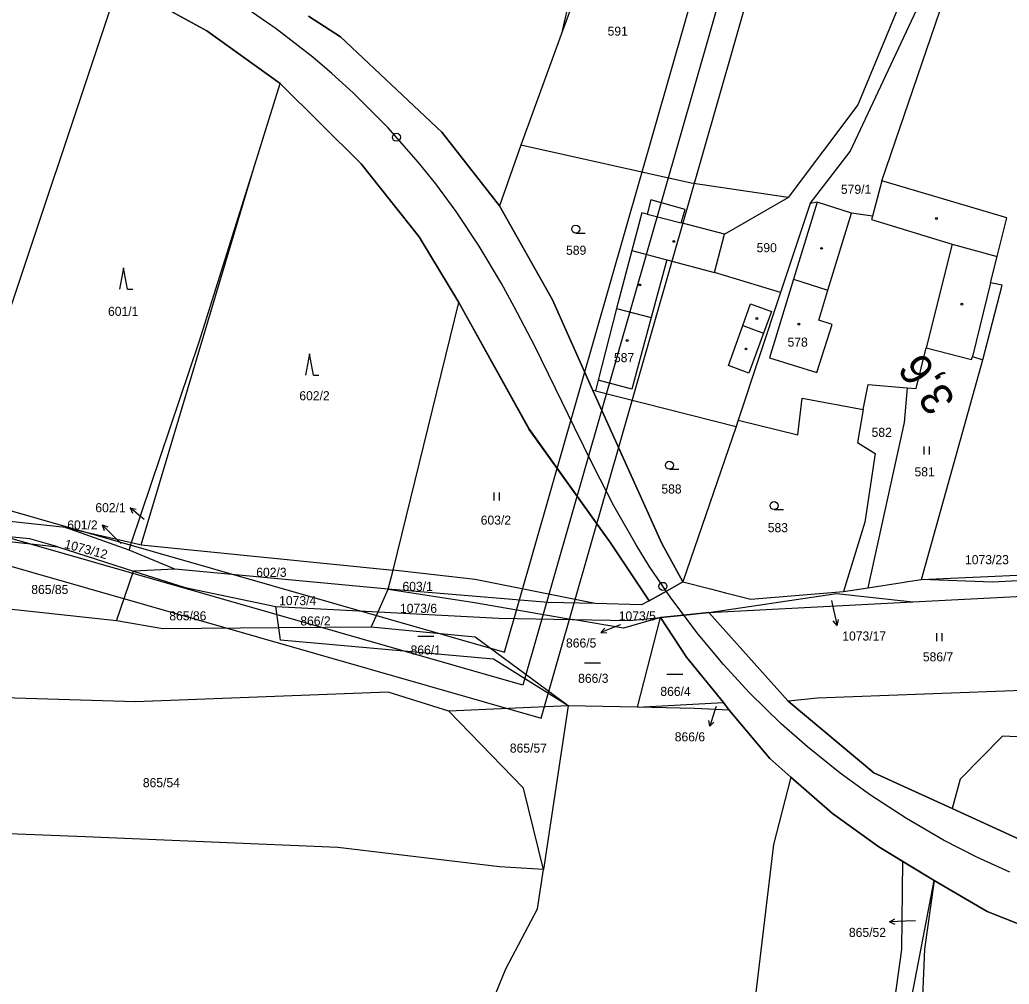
# Model space of a CAD drawing. Extents: x -738085 to -734306, y -1122197 to -1119753.
# Drawn here: x -736906 to -736720.5, y -1121765.8 to -1121585.1 of the extents above; entities that cross this region are included whole.
import ezdxf

# ---------------------------------------------------------------- set-up
doc = ezdxf.new("R2010")
doc.units = 0
for name, color, linetype in [('Hranice parcel', 7, 'Continuous'), ('Parcelní čísla', 7, 'Continuous'), ('Pop  PČ popisy', 7, 'Continuous'), ('SŽDC', 7, 'Continuous'), ('Vnitřní kresba', 7, 'Continuous'), ('Vrstva 1', 7, 'Continuous'), ('Vrstva 53', 7, 'Continuous'), ('Vrstva 7', 7, 'Continuous'), ('Značky budov', 7, 'Continuous'), ('Značky kultur', 7, 'Continuous')]:
    doc.layers.add(name, color=color, linetype=linetype)

msp = doc.modelspace()

# ---------------------------------------------------------------- linework, layer by layer
at = {"layer": 'Hranice parcel'}
for p, q in [((-736804.2, -1121587.16), (-736798.31, -1121561.29)), ((-736795.38, -1121563.11), (-736804.2, -1121587.16)), ((-736744.38, -1121615.25), (-736731.13, -1121576.64)), ((-736920.64, -1121677.71), (-736887.39, -1121578.1)), ((-736887.39, -1121578.1), (-736870.91, -1121587.14)), ((-736870.91, -1121587.14), (-736857.16, -1121597.03)), ((-736804.2, -1121587.16), (-736812.06, -1121608.56)), ((-736862.23, -1121613.22), (-736857.16, -1121597.03)), ((-736812.06, -1121608.56), (-736816.01, -1121619.92)), ((-736883.23, -1121683.48), (-736862.23, -1121613.22)), ((-736773.84, -1121625.27), (-736761.91, -1121618.36)), ((-736757.76, -1121619.52), (-736763.38, -1121636.17)), ((-736816.01, -1121619.92), (-736806.1, -1121637.54)), ((-736763.38, -1121636.17), (-736771.28, -1121660.12)), ((-736836, -1121688.2), (-736823.69, -1121638.07)), ((-736806.1, -1121637.54), (-736798.56, -1121654.54)), ((-736736.91, -1121689.98), (-736725.44, -1121648.79)), ((-736798.06, -1121654.63), (-736798.56, -1121654.54)), ((-736798.06, -1121654.63), (-736771.68, -1121661.3)), ((-736771.28, -1121660.12), (-736771.68, -1121661.3)), ((-736771.68, -1121661.3), (-736781.66, -1121690.42)), ((-736897.44, -1121680.24), (-736920.64, -1121677.71)), ((-736897.44, -1121680.24), (-736885.01, -1121683.07)), ((-736885.49, -1121684.49), (-736897.44, -1121680.24)), ((-736898.85, -1121683.84), (-736884.64, -1121688.4)), ((-736885.49, -1121684.49), (-736885.01, -1121683.07)), ((-736876.89, -1121688.05), (-736885.49, -1121684.49)), ((-736885.01, -1121683.07), (-736883.23, -1121683.48)), ((-736883.23, -1121683.48), (-736836, -1121688.2)), ((-736876.89, -1121688.05), (-736884.64, -1121688.4)), ((-736836.89, -1121691.81), (-736876.89, -1121688.05)), ((-736836.89, -1121691.81), (-736836, -1121688.2)), ((-736887.88, -1121697.71), (-736884.64, -1121688.4)), ((-736736.91, -1121689.98), (-736714.87, -1121688.97)), ((-736838.79, -1121696.05), (-736836.89, -1121691.81)), ((-736751.55, -1121692.22), (-736746.95, -1121691.53)), ((-736857.43, -1121699.06), (-736857.96, -1121695.06)), ((-736857.96, -1121695.06), (-736838.79, -1121696.05)), ((-736776.82, -1121696.15), (-736738.53, -1121694.16)), ((-736840.07, -1121698.92), (-736838.79, -1121696.05)), ((-736790.17, -1121713.93), (-736785.85, -1121697.11)), ((-736761.9, -1121712.81), (-736776.82, -1121696.15)), ((-736840.07, -1121698.92), (-736857.43, -1121699.06)), ((-736803.14, -1121713.67), (-736825.52, -1121714.65)), ((-736803.14, -1121713.67), (-736807.76, -1121744.34)), ((-736790.17, -1121713.93), (-736803.14, -1121713.67)), ((-736790.17, -1121713.93), (-736774.04, -1121713.02)), ((-736774.04, -1121713.02), (-736772.96, -1121714.48)), ((-736740.39, -1121742.85), (-736734.55, -1121746.43))]:
    msp.add_line(p, q, dxfattribs=at)
for points in [[(-736737.5, -1121573.48), (-736748.87, -1121600.98), (-736761.91, -1121618.36)], [(-736757.76, -1121619.52), (-736750.29, -1121609.72), (-736734.46, -1121575.99)], [(-736816.01, -1121619.92), (-736826.87, -1121606.1), (-736845.88, -1121588.28), (-736851.83, -1121584.35)], [(-736857.16, -1121597.03), (-736842, -1121612.07), (-736831.1, -1121625.74), (-736823.69, -1121638.07)], [(-736761.91, -1121618.36), (-736780.08, -1121615.71), (-736812.06, -1121608.56)], [(-736885.01, -1121683.07), (-736872.32, -1121645.4), (-736862.23, -1121613.22)], [(-736744.38, -1121615.25), (-736746.11, -1121621.84), (-736750.01, -1121621.31), (-736756.49, -1121619.27), (-736757.76, -1121619.52)], [(-736725.44, -1121648.79), (-736721.76, -1121634.82), (-736723.95, -1121634.36), (-736722.72, -1121629.46), (-736720.89, -1121622.16), (-736744.38, -1121615.25)], [(-736773.84, -1121625.27), (-736781.96, -1121623.14), (-736781.22, -1121620.6), (-736787.66, -1121618.81), (-736788.34, -1121621.5), (-736789.34, -1121621.24), (-736791.21, -1121628.32), (-736794.07, -1121639.16), (-736797.54, -1121652.6), (-736798.06, -1121654.63)], [(-736763.38, -1121636.17), (-736775.71, -1121632.4), (-736773.84, -1121625.27)], [(-736823.69, -1121638.07), (-736810.44, -1121661.83), (-736795.22, -1121683.12), (-736787.95, -1121693.96)], [(-736739.59, -1121654.03), (-736737.89, -1121654.18), (-736736.01, -1121646.58), (-736727.53, -1121648.73), (-736727.35, -1121648.19), (-736725.44, -1121648.79)], [(-736798.56, -1121654.54), (-736785.62, -1121683.26), (-736781.66, -1121690.42)], [(-736747.85, -1121658.12), (-736746.89, -1121653.43), (-736739.59, -1121654.03)], [(-736739.59, -1121654.03), (-736740.18, -1121660.52), (-736746.95, -1121691.53)], [(-736771.28, -1121660.12), (-736760.1, -1121662.86), (-736759.3, -1121656.01), (-736747.85, -1121658.12)], [(-736747.85, -1121658.12), (-736748.92, -1121664.28), (-736745.58, -1121666.34), (-736747.55, -1121679.23), (-736751.55, -1121692.22)], [(-736898.85, -1121683.84), (-736904.07, -1121682.33), (-736920.51, -1121680.8)], [(-736920.32, -1121682.51), (-736910.21, -1121682.63), (-736898.85, -1121683.84)], [(-736798.07, -1121694.5), (-736820.58, -1121689.98), (-736836, -1121688.2)], [(-736884.64, -1121688.4), (-736875, -1121691.49), (-736857.96, -1121695.06)], [(-736746.95, -1121691.53), (-736740.51, -1121690.54), (-736739.5, -1121690.38), (-736736.91, -1121689.98)], [(-736701.11, -1121689.29), (-736723.58, -1121690.47), (-736736.91, -1121689.98)], [(-736798.07, -1121694.5), (-736806.94, -1121694.27), (-736836.89, -1121691.81)], [(-736836.89, -1121691.81), (-736820.75, -1121694.29), (-736802.33, -1121697.47)], [(-736787.95, -1121693.96), (-736784.72, -1121692.14), (-736781.66, -1121690.42)], [(-736781.66, -1121690.42), (-736776.45, -1121691.74), (-736773.66, -1121692.45), (-736768.91, -1121693.66), (-736751.55, -1121692.22)], [(-736776.82, -1121696.15), (-736752.86, -1121692.61), (-736738.53, -1121694.16)], [(-736738.53, -1121694.16), (-736708.22, -1121692.59), (-736702.57, -1121692.29)], [(-736887.88, -1121697.71), (-736910.4, -1121695.27), (-736918.95, -1121695.03)], [(-736787.95, -1121693.96), (-736789.39, -1121694.72), (-736798.07, -1121694.5)], [(-736838.79, -1121696.05), (-736816.16, -1121697.22), (-736802.33, -1121697.47)], [(-736785.85, -1121697.11), (-736792.76, -1121699.13), (-736802.33, -1121697.47)], [(-736802.33, -1121697.47), (-736791.66, -1121697.67), (-736785.85, -1121697.11)], [(-736776.82, -1121696.15), (-736781.46, -1121696.64), (-736785.85, -1121697.11)], [(-736785.85, -1121697.11), (-736780.95, -1121704.53), (-736774.04, -1121713.02)], [(-736857.43, -1121699.06), (-736879.16, -1121699.24), (-736887.88, -1121697.71)], [(-736803.14, -1121713.67), (-736817.17, -1121704.92), (-736857.13, -1121701.35), (-736857.43, -1121699.06)], [(-736803.14, -1121713.67), (-736820.59, -1121700.79), (-736840.07, -1121698.92)], [(-736709.58, -1121710.45), (-736756.42, -1121712.25), (-736761.9, -1121712.81)], [(-736609.66, -1121712.27), (-736632.32, -1121710.21), (-736655.43, -1121722.35), (-736721.72, -1121719.32), (-736729.67, -1121727.41), (-736731.16, -1121732.89)], [(-736825.52, -1121714.65), (-736836.93, -1121711.11), (-736884.3, -1121712.91), (-736913.18, -1121712.05), (-736955.53, -1121711.24)], [(-736609.66, -1121712.27), (-736611.62, -1121744.93), (-736632.11, -1121748.77), (-736650.76, -1121751.05), (-736668.27, -1121750.12), (-736688.52, -1121747.94), (-736709.5, -1121742.83), (-736731.16, -1121732.89)], [(-736772.96, -1121714.48), (-736779.48, -1121714.14), (-736790.17, -1121713.93)], [(-736731.16, -1121732.89), (-736745.83, -1121726.21), (-736761.9, -1121712.81)], [(-736807.76, -1121744.34), (-736811.52, -1121729.1), (-736825.52, -1121714.65)], [(-736772.96, -1121714.48), (-736765.38, -1121723.5), (-736761.39, -1121727.01)], [(-736761.39, -1121727.01), (-736764.66, -1121739.64), (-736768.04, -1121767.89), (-736772.23, -1121792.88), (-736784.22, -1121832.99), (-736788.98, -1121849.83), (-736793.46, -1121869.19), (-736802.29, -1121890.54)], [(-736761.39, -1121727.01), (-736753.63, -1121733.84), (-736744.92, -1121740.07), (-736740.39, -1121742.85)], [(-736807.76, -1121744.34), (-736816.02, -1121743.84), (-736846.35, -1121740.22), (-736893.71, -1121738.2), (-736935.01, -1121736.61), (-736957.97, -1121734.16)], [(-736751.19, -1121812.6), (-736741.94, -1121768.76), (-736740.6, -1121759.31), (-736740.39, -1121742.85)], [(-736821.14, -1121795.91), (-736819.31, -1121773.82), (-736814.83, -1121762.98), (-736808.91, -1121751.71), (-736807.76, -1121744.34)], [(-736734.55, -1121746.43), (-736736.37, -1121759.3), (-736737.89, -1121796.72), (-736743.6, -1121792.61), (-736749.16, -1121817.29), (-736753.26, -1121836.34)], [(-736751.19, -1121812.6), (-736740.47, -1121777.31), (-736734.55, -1121746.43)], [(-736734.55, -1121746.43), (-736724.6, -1121752.2), (-736709.93, -1121758.04), (-736695.7, -1121762.6), (-736683.21, -1121764.75), (-736668.91, -1121765.12), (-736652.26, -1121764.66), (-736637.94, -1121762.04), (-736612.06, -1121753.19)]]:
    msp.add_lwpolyline(points, dxfattribs=at)
at = {"layer": 'Pop  PČ popisy'}
for p, q in [((-736882.98, -1121678.45), (-736885.28, -1121676.52)), ((-736885.28, -1121676.52), (-736884.19, -1121676.78)), ((-736885.28, -1121676.52), (-736884.83, -1121677.55)), ((-736882.68, -1121678.71), (-736882.98, -1121678.45)), ((-736888.4, -1121681.86), (-736890.52, -1121679.74)), ((-736890.52, -1121679.74), (-736889.46, -1121680.09)), ((-736890.52, -1121679.74), (-736890.17, -1121680.8)), ((-736886.99, -1121683.26), (-736888.4, -1121681.86)), ((-736753.81, -1121693.92), (-736753.42, -1121695.66)), ((-736753.42, -1121695.66), (-736752.74, -1121698.58)), ((-736752.74, -1121698.58), (-736752.48, -1121697.5)), ((-736794.23, -1121698.79), (-736797.01, -1121699.91)), ((-736797.01, -1121699.91), (-736796.27, -1121699.07)), ((-736793.38, -1121698.45), (-736794.23, -1121698.79)), ((-736752.74, -1121698.58), (-736753.46, -1121697.72)), ((-736797.01, -1121699.91), (-736795.9, -1121700)), ((-736775.42, -1121713.78), (-736775.7, -1121714.64)), ((-736775.7, -1121714.64), (-736776.63, -1121717.49)), ((-736776.63, -1121717.49), (-736776.79, -1121716.39)), ((-736776.63, -1121717.49), (-736775.84, -1121716.7)), ((-736742.91, -1121754.15), (-736741.93, -1121753.61)), ((-736739.91, -1121754.04), (-736742.91, -1121754.15)), ((-736742.91, -1121754.15), (-736741.89, -1121754.61)), ((-736738.01, -1121753.97), (-736739.91, -1121754.04))]:
    msp.add_line(p, q, dxfattribs=at)
at = {"layer": 'SŽDC'}
for p, q in [((-736887.39, -1121578.1), (-736870.91, -1121587.14)), ((-736870.91, -1121587.14), (-736857.16, -1121597.03)), ((-736857.16, -1121597.03), (-736842, -1121612.07)), ((-736806.1, -1121637.54), (-736816.01, -1121619.92)), ((-736798.56, -1121654.54), (-736806.1, -1121637.54))]:
    msp.add_line(p, q, dxfattribs=at)
for points in [[(-736816.01, -1121619.92), (-736826.87, -1121606.1), (-736845.88, -1121588.28), (-736851.83, -1121584.35)], [(-736842, -1121612.07), (-736831.1, -1121625.74), (-736823.69, -1121638.07)], [(-736823.69, -1121638.07), (-736810.44, -1121661.83), (-736795.22, -1121683.12), (-736787.95, -1121693.96)], [(-736781.66, -1121690.42), (-736785.62, -1121683.26), (-736798.56, -1121654.54)], [(-736787.95, -1121693.96), (-736784.72, -1121692.14), (-736781.66, -1121690.42)]]:
    msp.add_lwpolyline(points, dxfattribs=at)
at = {"layer": 'Vnitřní kresba'}
for p, q in [((-736756.49, -1121619.27), (-736760.91, -1121633.67)), ((-736754.45, -1121635.73), (-736750.01, -1121621.31)), ((-736788.34, -1121621.5), (-736781.96, -1121623.14)), ((-736746.11, -1121621.84), (-736746.31, -1121622.5)), ((-736746.31, -1121622.5), (-736731.17, -1121627.1)), ((-736791.21, -1121628.32), (-736784.68, -1121630.04)), ((-736731.17, -1121627.1), (-736736.01, -1121646.58)), ((-736731.17, -1121627.1), (-736722.72, -1121629.46)), ((-736784.68, -1121630.04), (-736787.59, -1121640.85)), ((-736784.68, -1121630.04), (-736775.71, -1121632.4)), ((-736760.91, -1121633.67), (-736765.43, -1121648.41)), ((-736760.91, -1121633.67), (-736754.45, -1121635.73)), ((-736723.95, -1121634.36), (-736727.35, -1121648.19)), ((-736756.18, -1121641.36), (-736754.45, -1121635.73)), ((-736794.07, -1121639.16), (-736787.59, -1121640.85)), ((-736770.42, -1121642.36), (-736768.97, -1121638.32)), ((-736768.97, -1121638.32), (-736765.05, -1121639.75)), ((-736765.05, -1121639.75), (-736766.54, -1121643.78)), ((-736787.59, -1121640.85), (-736791.21, -1121654.31)), ((-736753.69, -1121642.18), (-736756.18, -1121641.36)), ((-736773.12, -1121649.86), (-736770.42, -1121642.36)), ((-736770.42, -1121642.36), (-736766.54, -1121643.78)), ((-736756.55, -1121651.16), (-736753.69, -1121642.18)), ((-736766.54, -1121643.78), (-736769.31, -1121651.29)), ((-736765.43, -1121648.41), (-736756.55, -1121651.16)), ((-736769.31, -1121651.29), (-736773.12, -1121649.86)), ((-736791.21, -1121654.31), (-736797.54, -1121652.6))]:
    msp.add_line(p, q, dxfattribs=at)
at = {"layer": 'Vrstva 1'}
for points in [[(-736726.43, -1121430.48), (-737533.93, -1121199.12), (-737615.73, -1121484.62), (-736808.23, -1121715.98)], [(-737530.5, -1121205.3), (-736732.61, -1121433.9), (-736811.65, -1121709.79), (-737609.54, -1121481.19)], [(-736738.79, -1121437.33), (-737330, -1121267.94), (-737406.29, -1121534.23), (-736815.08, -1121703.62)]]:
    msp.add_lwpolyline(points, close=True, dxfattribs=at)
msp.add_lwpolyline([(-736720.34, -1121744.85), (-736726.52, -1121742.02), (-736732.78, -1121738.82), (-736739.75, -1121734.78), (-736746.5, -1121730.38), (-736752.15, -1121726.29), (-736758.31, -1121721.33), (-736763.2, -1121717.03), (-736769.17, -1121711.2), (-736774.04, -1121705.9), (-736778.8, -1121700.25), (-736783.92, -1121693.44), (-736787.95, -1121687.49), (-736790.42, -1121683.49), (-736794.6, -1121676.14), (-736798.44, -1121668.75), (-736802, -1121661.51), (-736805.53, -1121654.2), (-736809.5, -1121646.11), (-736813.27, -1121638.85), (-736815.64, -1121634.52), (-736819.82, -1121627.48), (-736824.16, -1121620.98), (-736827.96, -1121615.83), (-736831.21, -1121611.8), (-736836.97, -1121605.25), (-736843.45, -1121598.76), (-736847.45, -1121595.12), (-736851.06, -1121592.07), (-736857.9, -1121586.77), (-736865.18, -1121581.77)], dxfattribs=at)
at = {"layer": 'Vrstva 53'}
for points in [[(-736851.83, -1121584.35), (-736845.88, -1121588.28), (-736826.87, -1121606.1), (-736816.01, -1121619.92), (-736806.08, -1121637.54), (-736798.56, -1121654.54), (-736785.61, -1121683.26), (-736781.66, -1121690.42), (-736784.72, -1121692.14), (-736787.95, -1121693.96), (-736795.22, -1121683.12), (-736810.45, -1121661.83), (-736823.69, -1121638.07), (-736831.1, -1121625.74), (-736842, -1121612.07), (-736857.16, -1121597.03), (-736870.91, -1121587.14), (-736887.39, -1121578.1)], [(-736776.82, -1121696.15), (-736761.9, -1121712.81), (-736745.83, -1121726.21), (-736731.16, -1121732.89), (-736709.49, -1121742.83), (-736688.52, -1121747.94), (-736668.27, -1121750.12), (-736650.76, -1121751.05), (-736632.11, -1121748.77), (-736611.65, -1121744.93), (-736609.66, -1121712.27), (-736609.49, -1121709.44), (-736590.63, -1121711.66), (-736571.91, -1121713.45), (-736567.16, -1121709.27), (-736561.91, -1121703.6), (-736552.9, -1121693.88), (-736544.38, -1121684.19), (-736507.68, -1121632.57), (-736475.27, -1121586.19)], [(-736552.55, -1121725.89), (-736579.86, -1121741.91), (-736592.94, -1121747.03), (-736612.06, -1121753.19), (-736637.94, -1121762.04), (-736652.26, -1121764.66), (-736668.91, -1121765.12), (-736683.21, -1121764.75), (-736695.7, -1121762.6), (-736709.93, -1121758.04), (-736724.6, -1121752.2), (-736734.55, -1121746.43), (-736744.92, -1121740.07), (-736753.63, -1121733.84), (-736761.39, -1121727.01), (-736765.38, -1121723.5), (-736772.96, -1121714.48), (-736774.04, -1121713.02), (-736780.95, -1121704.53), (-736785.85, -1121697.11), (-736781.46, -1121696.64), (-736776.82, -1121696.15)]]:
    msp.add_lwpolyline(points, dxfattribs=at)
at = {"layer": 'Vrstva 7'}
for centre in [(-736835.36, -1121607.08), (-736785.39, -1121691.26)]:
    msp.add_circle(centre, 0.75, dxfattribs=at)
at = {"layer": 'Značky budov'}
for centre in [(-736734.13, -1121622.32), (-736783.37, -1121626.6), (-736755.64, -1121627.9), (-736789.7, -1121634.77), (-736729.37, -1121638.38), (-736767.79, -1121641.07), (-736759.91, -1121642.1), (-736792.1, -1121645.16), (-736769.82, -1121646.76)]:
    msp.add_circle(centre, 0.175, dxfattribs=at)
at = {"layer": 'Značky kultur'}
for p, q in [((-736801.73, -1121625.04), (-736799.98, -1121625.04)), ((-736886.51, -1121631.56), (-736887.26, -1121635.56)), ((-736885.76, -1121635.56), (-736886.51, -1121631.56)), ((-736885.76, -1121635.56), (-736884.76, -1121635.56)), ((-736851.69, -1121647.68), (-736852.44, -1121651.68)), ((-736850.94, -1121651.68), (-736851.69, -1121647.68)), ((-736850.94, -1121651.68), (-736849.94, -1121651.68)), ((-736736.44, -1121666.57), (-736736.44, -1121665.07)), ((-736735.44, -1121666.57), (-736735.44, -1121665.07)), ((-736784.19, -1121669.31), (-736782.44, -1121669.31)), ((-736817.01, -1121675.16), (-736817.01, -1121673.66)), ((-736816.01, -1121675.16), (-736816.01, -1121673.66)), ((-736764.56, -1121676.88), (-736762.81, -1121676.88)), ((-736831.38, -1121700.58), (-736828.38, -1121700.58)), ((-736734.01, -1121701.55), (-736734.01, -1121700.05)), ((-736733.01, -1121701.55), (-736733.01, -1121700.05)), ((-736800.08, -1121705.58), (-736797.08, -1121705.58)), ((-736784.67, -1121707.71), (-736781.67, -1121707.71))]:
    msp.add_line(p, q, dxfattribs=at)
for centre in [(-736801.73, -1121624.29), (-736784.19, -1121668.56), (-736764.56, -1121676.13)]:
    msp.add_circle(centre, 0.75, dxfattribs=at)

# ---------------------------------------------------------------- texts
at = {"layer": 'Parcelní čísla'}
for s, p in [('591', (-736795.77, -1121588.04)), ('579/1', (-736752.02, -1121617.68)), ('590', (-736767.83, -1121628.63)), ('589', (-736803.56, -1121629.11)), ('601/1', (-736889.44, -1121640.56)), ('578', (-736762.03, -1121646.33)), ('587', (-736794.58, -1121649.24)), ('602/2', (-736853.57, -1121656.38)), ('582', (-736746.27, -1121663.24)), ('581', (-736738.22, -1121670.64)), ('588', (-736785.69, -1121673.86)), ('602/1', (-736891.82, -1121677.36)), ('601/2', (-736897.08, -1121680.6)), ('603/2', (-736819.56, -1121679.7)), ('583', (-736765.74, -1121681.11)), ('1073/23', (-736728.75, -1121687.11)), ('602/3', (-736861.65, -1121689.48)), ('865/85', (-736903.83, -1121692.7)), ('603/1', (-736834.23, -1121692.11)), ('1073/4', (-736857.36, -1121694.79)), ('1073/6', (-736834.7, -1121696.23)), ('865/86', (-736877.95, -1121697.64)), ('866/2', (-736853.39, -1121698.59)), ('1073/5', (-736793.68, -1121697.65)), ('866/5', (-736803.57, -1121702.73)), ('1073/17', (-736751.77, -1121701.42)), ('866/1', (-736832.71, -1121704.04)), ('586/7', (-736736.66, -1121705.32)), ('866/3', (-736801.3, -1121709.35)), ('866/4', (-736785.88, -1121711.8)), ('866/6', (-736783.18, -1121720.32)), ('865/57', (-736814.1, -1121722.43)), ('865/54', (-736882.91, -1121728.91)), ('865/52', (-736750.52, -1121756.98))]:
    msp.add_text(s, height=1.7, dxfattribs=at).set_placement(p)
msp.add_text('1073/12', height=1.7, rotation=345, dxfattribs=at).set_placement((-736897.74, -1121684.06))
at = {"layer": 'Vrstva 7'}
msp.add_text('3,6', height=6, rotation=124.1319, dxfattribs=at).set_placement((-736730.36, -1121656.36))

doc.saveas('drawing.dxf')
